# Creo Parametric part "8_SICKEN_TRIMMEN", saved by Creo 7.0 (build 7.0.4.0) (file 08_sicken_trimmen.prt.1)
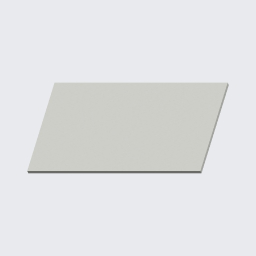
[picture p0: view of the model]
Units: millimeter Kilogram Sec (mmKs); MM, KILOGRAM, SECS
Materials in the file: S235JRG2

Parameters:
  SMT_PART_BEND_ALLOW_FACTOR_TYPE = "Y FACTOR"
  SMT_DFLT_RADIUS_SIDE = "Inside"
  SMT_DFLT_CRNR_REL_TYPE = "V Notch"
  SMT_DFLT_CRNR_REL_DEPTH_TYPE = "Blind"
  SMT_DFLT_BEND_REL_TYPE = "Rip"
  SMT_DFLT_BEND_REL_DEPTH_TYPE = "Up to Bend"
  SMT_DFLT_EDGE_TREA_TYPE = "Open"
  PTC_MATERIAL_NAME = "S235JRG2"
  BENENNUNG = "XXX"
  DATUM = "XX.XX.XX"
  ERSTELLER = "ARINDA"
  TEILETYP = "Fertigungsteil"
  SELECT_EN_NAME = "S235JRG2"
  SELECT_DIN_NAME = "RSt37-2"
  SELECT_DIN_NUMBER = "1.0038"
  SELECT_ASTM_NAME = "A 283 M Grade 2"
  MATERIAL_GROUP = "ME_ST_Baustahl"
  STANDARD_EN_DELIVERYSPEC = "DIN EN 10025"
  STANDARD_DIN_DELIVERYSPEC = "DIN 17100"

Other parameters: SMT_THICKNESS, SMT_PART_BEND_ALLOWANCE_FACTOR, SMT_UPDATE_BEND_ALLOW_INFO, SMT_DFLT_BEND_RADIUS, SMT_DFLT_BEND_ANGLE, SMT_DFLT_CRNR_REL_WIDTH, SMT_DFLT_CRNR_REL_DEPTH, SMT_DFLT_BEND_REL_WIDTH, SMT_DFLT_BEND_REL_DEPTH, SMT_DFLT_BEND_REL_ANGLE, SMT_GAP, SMT_DFLT_EDGE_TREA_WIDTH, SMT_DFLT_MITER_CUT_WIDTH, SMT_DFLT_MITER_CUT_OFFSET, MASSE, SMT_DFLT_BEND_REL_LENGTH

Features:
  1. coordinate system
  2. datum plane "DTM1", "T_RECHTS_Y-Z"
  3. datum plane "DTM2", "T_OBEN_X-Z"
  4. datum plane "DTM3", "T_VORNE_X-Y"
  5. datum axis "A_1"
  6. datum axis "A_2"
  7. datum axis "A_3"
  8. fill "Planar 1(Erste Lasche)"

Other named items: T_BASIS, A_X-ACHSE, A_Y-ACHSE, A_Z-ACHSE

Layers: 00_STD-ACHSEN, 00_STD-EBENEN, 00_STD-KOORDSYS, SAMMELFLÄCHEN, VOLUMENGEOMETRIE

Surfaces: 6 plane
